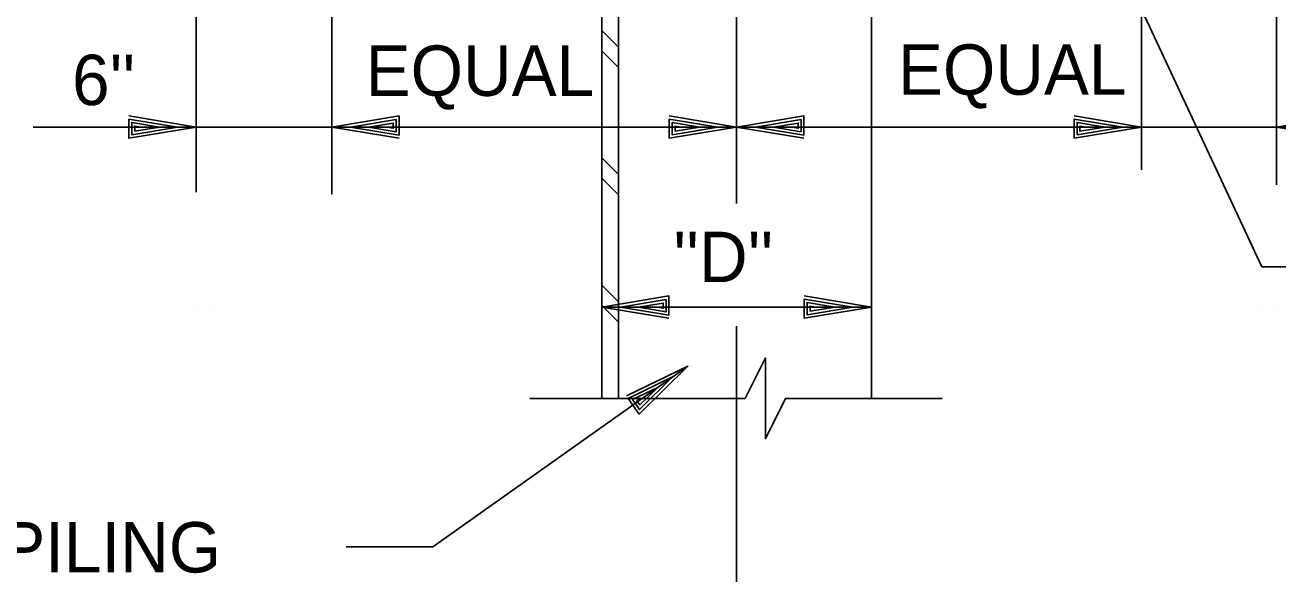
# Model space of a CAD drawing. Extents: x 22411.4 to 22495.4, y 22369.6 to 22415.
# Drawn here: x 22426.823 to 22431.465, y 22387.866 to 22389.928 of the extents above; entities that cross this region are included whole.
import ezdxf

# ---------------------------------------------------------------- set-up
doc = ezdxf.new("R2010")
doc.units = 0
for name, color, linetype in [('Level 1', 7, 'Continuous'), ('Level 2', 7, 'Continuous'), ('Level 4', 7, 'Continuous'), ('Level 8', 7, 'Continuous')]:
    doc.layers.add(name, color=color, linetype=linetype)

msp = doc.modelspace()

# ---------------------------------------------------------------- linework, layer by layer
at = {"layer": 'Level 1'}
for p, q in [((22429.4594, 22389.2676), (22429.4594, 22398.5817)), ((22427.4571, 22392.0056), (22427.4571, 22389.309)), ((22431.4594, 22391.9886), (22431.4594, 22389.3366)), ((22427.9594, 22391.3046), (22427.9594, 22389.3021)), ((22430.9594, 22391.3175), (22430.9594, 22389.3918)), ((22426.8524, 22389.5499), (22427.4571, 22389.5499)), ((22427.4571, 22389.5499), (22427.9594, 22389.5499)), ((22427.9594, 22389.5499), (22429.4594, 22389.5499)), ((22429.39, 22389.5499), (22429.39, 22389.5499)), ((22429.4594, 22389.5499), (22429.4594, 22389.5499)), ((22429.4594, 22389.5499), (22429.4594, 22389.5499)), ((22430.9594, 22389.5499), (22429.4594, 22389.5499)), ((22429.5287, 22389.5499), (22429.5287, 22389.5499)), ((22430.89, 22389.5499), (22430.89, 22389.5499)), ((22430.9594, 22389.5499), (22430.9594, 22389.5499)), ((22431.4594, 22389.5499), (22430.9594, 22389.5499)), ((22432.1255, 22389.5499), (22431.4594, 22389.5499)), ((22427.4571, 22388.8832), (22427.4571, 22388.8832)), ((22427.5265, 22388.8832), (22427.5265, 22388.8832)), ((22429.9594, 22388.8832), (22428.9594, 22388.8832)), ((22429.39, 22388.8832), (22429.39, 22388.8832)), ((22429.4594, 22388.8832), (22429.4594, 22388.8832)), ((22429.4594, 22388.8832), (22429.4594, 22388.8832)), ((22429.5287, 22388.8832), (22429.5287, 22388.8832)), ((22431.39, 22388.8832), (22431.39, 22388.8832)), ((22431.39, 22388.8832), (22431.39, 22388.8832)), ((22431.39, 22388.8832), (22431.39, 22388.8832)), ((22431.4594, 22388.8832), (22431.4594, 22388.8832)), ((22431.4594, 22388.8832), (22431.4594, 22388.8832)), ((22431.4594, 22388.8832), (22431.4594, 22388.8832)), ((22429.4594, 22387.8659), (22429.4594, 22388.8124)), ((22429.2785, 22388.6649), (22429.2785, 22388.6649)), ((22429.2219, 22388.6248), (22429.2219, 22388.6248)), ((22428.6934, 22388.5455), (22429.4914, 22388.5455)), ((22429.6409, 22388.5455), (22430.2206, 22388.5455))]:
    msp.add_line(p, q, dxfattribs=at)
msp.add_lwpolyline([(22429.4914, 22388.5455), (22429.5659, 22388.6955), (22429.5659, 22388.3958), (22429.6409, 22388.5455)], dxfattribs=at)
at = {"layer": 'Level 2'}
for p, q in [((22428.9594, 22388.5455), (22428.9594, 22391.533)), ((22429.0219, 22388.5455), (22429.0219, 22391.533)), ((22429.9594, 22388.5455), (22429.9594, 22390.4475))]:
    msp.add_line(p, q, dxfattribs=at)
for points in [[(22431.6506, 22389.0326), (22431.4055, 22389.0326), (22430.2374, 22391.5323)], [(22427.2078, 22389.5912), (22427.4571, 22389.5499), (22427.2078, 22389.5086), (22427.2078, 22389.5792), (22427.3878, 22389.5499), (22427.2185, 22389.5219), (22427.2185, 22389.5672), (22427.3211, 22389.5499), (22427.2291, 22389.5352), (22427.2291, 22389.5539), (22427.2518, 22389.5499)], [(22428.2087, 22389.5086), (22427.9594, 22389.5499), (22428.2087, 22389.5912), (22428.2087, 22389.5206), (22428.0287, 22389.5499), (22428.198, 22389.5779), (22428.198, 22389.5326), (22428.0954, 22389.5499), (22428.1874, 22389.5646), (22428.1874, 22389.5459), (22428.1647, 22389.5499)], [(22429.21, 22389.5912), (22429.4594, 22389.5499), (22429.21, 22389.5086), (22429.21, 22389.5792), (22429.39, 22389.5499), (22429.2207, 22389.5219), (22429.2207, 22389.5672), (22429.3234, 22389.5499), (22429.2314, 22389.5352), (22429.2314, 22389.5539), (22429.254, 22389.5499)], [(22429.7087, 22389.5086), (22429.4594, 22389.5499), (22429.7087, 22389.5912), (22429.7087, 22389.5206), (22429.5287, 22389.5499), (22429.698, 22389.5779), (22429.698, 22389.5326), (22429.5954, 22389.5499), (22429.6874, 22389.5646), (22429.6874, 22389.5459), (22429.6647, 22389.5499)], [(22430.71, 22389.5912), (22430.9594, 22389.5499), (22430.71, 22389.5086), (22430.71, 22389.5792), (22430.89, 22389.5499), (22430.7207, 22389.5219), (22430.7207, 22389.5672), (22430.8234, 22389.5499), (22430.7314, 22389.5352), (22430.7314, 22389.5539), (22430.754, 22389.5499)], [(22431.7087, 22389.5086), (22431.4594, 22389.5499), (22431.7087, 22389.5912), (22431.7087, 22389.5206), (22431.5287, 22389.5499), (22431.698, 22389.5779), (22431.698, 22389.5326), (22431.5954, 22389.5499), (22431.6874, 22389.5646), (22431.6874, 22389.5459), (22431.6647, 22389.5499)], [(22429.2087, 22388.8419), (22428.9594, 22388.8832), (22429.2087, 22388.9246), (22429.2087, 22388.8539), (22429.0287, 22388.8832), (22429.198, 22388.9112), (22429.198, 22388.8659), (22429.0954, 22388.8832), (22429.1874, 22388.8979), (22429.1874, 22388.8792), (22429.1647, 22388.8832)], [(22429.71, 22388.9246), (22429.9594, 22388.8832), (22429.71, 22388.8419), (22429.71, 22388.9126), (22429.89, 22388.8832), (22429.7207, 22388.8552), (22429.7207, 22388.9006), (22429.8234, 22388.8832), (22429.7314, 22388.8686), (22429.7314, 22388.8872), (22429.754, 22388.8832)], [(22428.013, 22387.9962), (22428.3335, 22387.9962), (22429.2785, 22388.6649)], [(22429.0511, 22388.5546), (22429.2785, 22388.6649), (22429.0988, 22388.4871), (22429.058, 22388.5448), (22429.2219, 22388.6248), (22429.0998, 22388.5042), (22429.0737, 22388.5412), (22429.1675, 22388.5863), (22429.1008, 22388.5212), (22429.0901, 22388.5364), (22429.1109, 22388.5463)]]:
    msp.add_lwpolyline(points, dxfattribs=at)
at = {"layer": 'Level 8'}
for p, q in [((22427.3878, 22389.5499), (22427.3878, 22389.5499)), ((22427.4571, 22389.5499), (22427.4571, 22389.5499)), ((22427.9594, 22389.5499), (22427.9594, 22389.5499)), ((22428.0287, 22389.5499), (22428.0287, 22389.5499)), ((22429.39, 22389.5499), (22429.39, 22389.5499)), ((22429.4594, 22389.5499), (22429.4594, 22389.5499)), ((22429.4594, 22389.5499), (22429.4594, 22389.5499)), ((22429.5287, 22389.5499), (22429.5287, 22389.5499)), ((22430.89, 22389.5499), (22430.89, 22389.5499)), ((22430.9594, 22389.5499), (22430.9594, 22389.5499)), ((22431.4594, 22389.5499), (22431.4594, 22389.5499)), ((22428.9594, 22388.8832), (22428.9594, 22388.8832)), ((22429.0287, 22388.8832), (22429.0287, 22388.8832)), ((22429.89, 22388.8832), (22429.89, 22388.8832)), ((22429.9594, 22388.8832), (22429.9594, 22388.8832))]:
    msp.add_line(p, q, dxfattribs=at)
for points in [[(22429.0219, 22389.8456), (22428.9594, 22389.9081)], [(22429.0219, 22389.7702), (22428.9594, 22389.8327)], [(22429.0219, 22389.3742), (22428.9594, 22389.4367)], [(22429.0219, 22389.2988), (22428.9594, 22389.3613)], [(22429.0219, 22388.9028), (22428.9594, 22388.9653)], [(22429.0219, 22388.8274), (22428.9594, 22388.8899)]]:
    msp.add_lwpolyline(points, dxfattribs=at)

# ---------------------------------------------------------------- texts
at = {"layer": 'Level 4'}
for s, height, p in [('EQUAL', 0.18667, (22428.085, 22389.6655)), ('EQUAL', 0.18667, (22430.0573, 22389.6696)), ("6''", 0.18667, (22426.9972, 22389.6314)), ("''D''", 0.18667, (22429.2246, 22388.9759)), ('STEEL SHEET PILING', 0.186667, (22424.9695, 22387.9008))]:
    msp.add_text(s, height=height, dxfattribs=at).set_placement(p)

doc.saveas('drawing.dxf')
